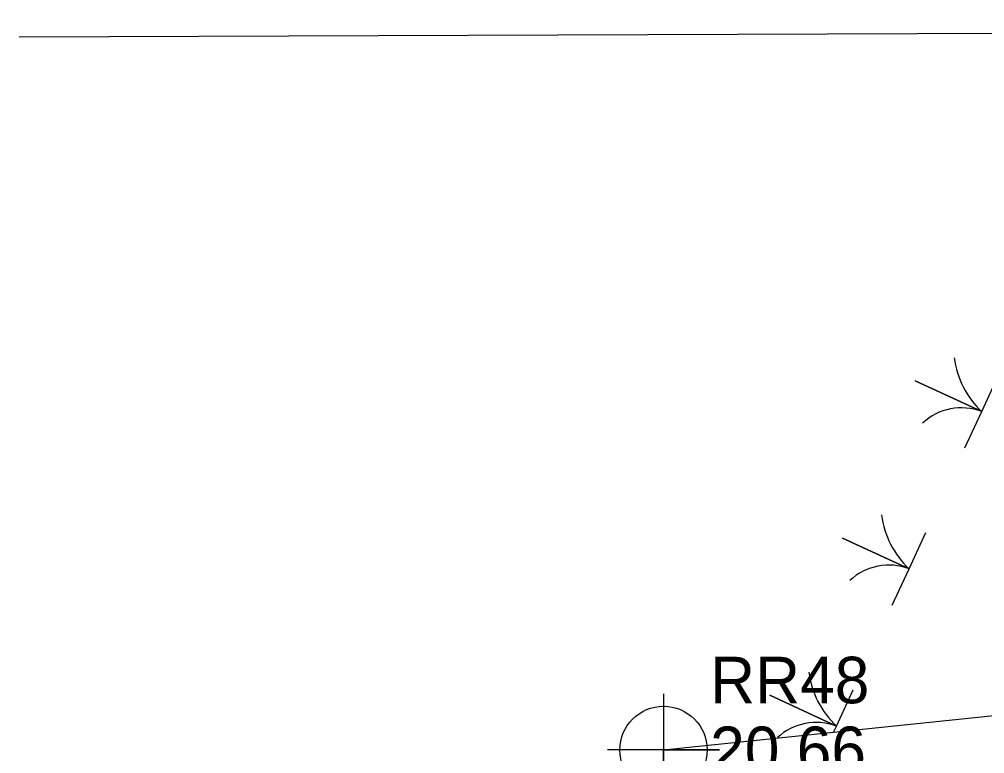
# Model space of a CAD drawing. Extents: x 2532037 to 2533565, y 713396 to 716867.
# Drawn here: x 2532538.1 to 2532589.9, y 715515.5 to 715554.9 of the extents above; entities that cross this region are included whole.
import ezdxf

# ---------------------------------------------------------------- set-up
doc = ezdxf.new("R2010")
doc.units = 0
for name, color, linetype in [('Exist Environmental Wetland Boundary', 7, 'Continuous'), ('Exist Environmental Wetland Boundary Cogo Elevation', 7, 'Continuous'), ('Exist Environmental Wetland Boundary Cogo Number', 7, 'Continuous'), ('Exist Environmental Wetland Boundary Cogo Point CELL', 7, 'Continuous'), ('Exist Property Line', 7, 'Continuous'), ('Scratch_Level_1', 7, 'Continuous')]:
    doc.layers.add(name, color=color, linetype=linetype)

msp = doc.modelspace()

# ---------------------------------------------------------------- linework, layer by layer
at = {"layer": 'Exist Environmental Wetland Boundary'}
msp.add_line((2532572.673, 715515.659), (2532625.543, 715521.155), dxfattribs=at)
at = {"layer": 'Exist Environmental Wetland Boundary Cogo Point CELL'}
msp.add_lwpolyline([(2532572.673, 715518.659), (2532572.673, 715512.659), (2532572.673, 715515.659), (2532575.673, 715515.659), (2532569.673, 715515.659)], dxfattribs=at)
msp.add_circle((2532572.673, 715515.659), 2.344, dxfattribs=at)
at = {"layer": 'Exist Property Line'}
msp.add_line((2532798.465, 715554.88), (2532538.102, 715553.917), dxfattribs=at)
at = {"layer": 'Scratch_Level_1'}
for points in [[(2532588.849, 715531.871), (2532589.751, 715533.823), (2532586.169, 715535.477), (2532589.751, 715533.823), (2532590.652, 715535.776)], [(2532584.951, 715523.426), (2532585.852, 715525.379), (2532582.27, 715527.032), (2532585.852, 715525.379), (2532586.753, 715527.331)], [(2532581.803, 715516.608), (2532581.954, 715516.935), (2532578.372, 715518.588), (2532581.954, 715516.935), (2532582.855, 715518.887)]]:
    msp.add_lwpolyline(points, dxfattribs=at)
for centre, radius, start, end in [((2532593.038, 715537.329), 4.806, 187.3464, 226.8412), ((2532588.667, 715530.946), 3.075, 69.3593, 132.7539), ((2532589.139, 715528.884), 4.806, 187.3464, 226.8412), ((2532584.768, 715522.502), 3.075, 69.3593, 132.7539), ((2532585.241, 715520.44), 4.806, 187.3464, 226.8412), ((2532580.87, 715514.057), 3.075, 69.3593, 132.7539)]:
    msp.add_arc(centre, radius, start, end, dxfattribs=at)

# ---------------------------------------------------------------- texts
at = {"layer": 'Exist Environmental Wetland Boundary Cogo Elevation'}
msp.add_text('20.66', height=2.5, dxfattribs=at).set_placement((2532575.173, 715514.409))
at = {"layer": 'Exist Environmental Wetland Boundary Cogo Number'}
msp.add_text('RR48', height=2.5, dxfattribs=at).set_placement((2532575.173, 715518.159))

doc.saveas('drawing.dxf')
